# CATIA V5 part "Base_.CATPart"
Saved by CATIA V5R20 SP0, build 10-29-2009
Part number: Base_
Bounding box of the stored display mesh (mm): x -10 to 50, y -87.915 to 10, z -2.5 to 10
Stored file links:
  C:\Users\Admin\Desktop\IAO\Base_.CATPart
  C:\Users\Admin\Desktop\IAO\Ass_4barres.CATProduct
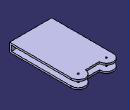
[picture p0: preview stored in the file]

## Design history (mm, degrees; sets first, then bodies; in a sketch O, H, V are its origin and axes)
External parameters (linked from other documents)
  `External.Longueur de la barre 1` = 40 mm
Set1
  Sketch1 on Plane1, origin (0, 0, 0), H (1, 0, 0), V (0, 1, 0)
    arc A1 centre (0, 0) radius 10 from (10, 0) to (-10, 0) ccw
    line L1 (-10, 0) -> (-10, -87.915)
    point P1 (-10, 0)
    line L2 (-10, -87.915) -> (50, -87.915)
    line L3 (50, -87.915) -> (50, 0)
    arc A2 centre (40, 0) radius 10 from (50, 0) to (30, 0) ccw
    point P5 (40, 0)
    line L4 (30, 0) -> (10, 0)
    point P6 (30, 0)
    reference projected point E1 (0, 0) from Point1
    reference projected point E2 (40, 0) from Point2
    reference projected line E3 (0, 0) -> (40, 0) from Line1
    radius A1 = 10
    radius A2 = 10
    distance E3 L2 = 87.915 {= ((2+sqrt(28) )/4)*`External.Longueur de la barre 1`+15mm}
    coincidence: P1 H, P5 H, P6 H
    tangency: L1 A1, L3 A2
    horizontal: L2 H, L4 H
    vertical: L3 V
    concentricity: E1 A1, E2 A2
Set2
  Plane1 "Plan ref": linked copy from another document
  Point1 "Point A": linked copy from another document
  Point2 "Point D": linked copy from another document
  Line1 "Barre 1": linked copy from another document
Body1 (main body)
  Pad1: profile Sketch1, direction (0, 0, -1), length 2.5, opposite side length 10
  Sketch2 on start face of Pad1, origin (43.1664, -8.8468, 10), H (1, 0, 0), V (0, 1, 0)
    point P1 (-3.1664, 8.8468)
    reference projected arc E1 centre (-3.1664, 8.8468) radius 10 from (6.8336, 8.8468) to (-13.1664, 8.8468) ccw from edge [face of Pad1 from Sketch1.A2 | start face of Pad1]
    concentricity: P1 E1
  Hole1: placed by Sketch2, at (40, 0, 10) direction (0, 0, -1), diameter 2.5, through (limit type 6)
  Sketch3 on end face of Pad1, origin (0.3497, 3.8268, -2.5), H (1, 0, 0), V (0, -1, 0)
    point P1 (-0.3497, 3.8268)
    reference projected point E1 (-0.3497, 3.8268) from Point1
    coincidence: E1 P1
  Hole2: placed by Sketch3, at (0, 0, -2.5) direction (0, 0, 1), diameter 2.5, through (limit type 6)
  Sketch4 on face of Pad1 from Sketch1.L1, origin (-10, 0, 0), H (0, -1, 0), V (0, 0, 1)
    line L1 (-34.585, 7.5) -> (85.415, 7.5)
    line L2 (85.415, 7.5) -> (85.415, 0)
    line L3 (85.415, 0) -> (-34.585, 0)
    line L4 (-34.585, 0) -> (-34.585, 7.5)
    point P3 (85.415, 0)
    reference projected line E1 (0, 10) -> (103.1174, 10) from edge [face of Pad1 from Sketch1.L1 | start face of Pad1]
    reference projected line E2 (87.915, 10) -> (87.915, -2.5) from edge [face of Pad1 from Sketch1.L1 | face of Pad1 from Sketch1.L2]
    distance L1 E1 = 2.5
    distance L2 E2 = 2.5
    distance L4 L2 = 120
    horizontal: L1 H, L3 H
    vertical: L2 V, L4 V
    coincidence: P3 H
  Pocket1: profile Sketch4, direction (1, 0, 0), through (limit type 6)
